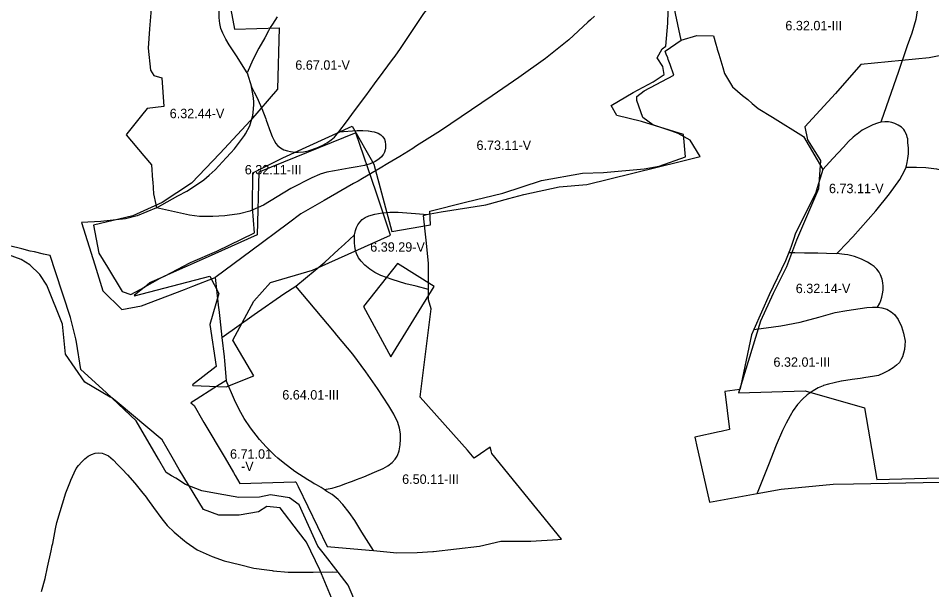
# Model space of a CAD drawing. Extents: x -555156 to -540209, y -1046851 to -1035695.
# Drawn here: x -542138 to -541169, y -1040382 to -1039776 of the extents above; entities that cross this region are included whole.
import ezdxf

# ---------------------------------------------------------------- set-up
doc = ezdxf.new("R2010")
doc.units = 0
for name, color, linetype in [('Vrstva 27', 7, 'Continuous'), ('Vrstva 28', 7, 'Continuous'), ('Vrstva 29', 7, 'Continuous')]:
    doc.layers.add(name, color=color, linetype=linetype)

msp = doc.modelspace()

# ---------------------------------------------------------------- linework, layer by layer
at = {"layer": 'Vrstva 28'}
for points in [[(-541895.16, -1039834.05), (-541906.66, -1039815.74), (-541914.31, -1039804.08), (-541917.9, -1039798.1), (-541921.04, -1039791.98), (-541923.13, -1039786.89), (-541924.32, -1039781.66), (-541924.61, -1039778.6), (-541924.92, -1039775.39), (-541924.97, -1039774.19), (-541925.22, -1039768.66), (-541924.32, -1039761.64), (-541921.93, -1039754.46), (-541917.9, -1039746.69), (-541913.27, -1039739.37), (-541909.09, -1039731.3), (-541907, -1039724.57), (-541905.35, -1039717.4), (-541904.56, -1039692.35), (-541904.34, -1039685.44), (-541904.65, -1039640.7)], [(-541797.96, -1039896.63), (-541789.75, -1039885.71), (-541784.17, -1039878.2), (-541782.31, -1039875.69), (-541769.44, -1039858.36), (-541760.16, -1039845.73), (-541750.87, -1039833.08), (-541741.18, -1039819.9), (-541738.38, -1039816.09), (-541732.54, -1039808.14), (-541707.95, -1039771.07), (-541678.94, -1039734.2), (-541666.43, -1039717.94), (-541658.62, -1039709.58), (-541654.1, -1039705.05), (-541648.89, -1039700.86), (-541641.72, -1039695.83), (-541633.87, -1039690.45), (-541622.3, -1039683.99), (-541614.45, -1039680.24), (-541605.83, -1039676.31), (-541589.27, -1039669.22)], [(-541341.55, -1039665.35), (-541304.33, -1039663.28), (-541293.54, -1039663.28), (-541280.69, -1039664.32), (-541267.4, -1039666.27), (-541256.35, -1039668.96), (-541242.01, -1039673.59), (-541231.7, -1039678.22), (-541223.19, -1039682.82), (-541214.67, -1039688.8), (-541206.31, -1039695.82), (-541199.14, -1039703.89), (-541194.3, -1039713.43), (-541193.61, -1039714.8), (-541190.02, -1039723.48), (-541188.23, -1039727.8), (-541185.69, -1039739.31), (-541183.6, -1039750.97), (-541183.45, -1039759.75), (-541184.2, -1039768.27), (-541185.54, -1039777.23), (-541189.88, -1039791.73)], [(-541434.57, -1039799.28), (-541444.21, -1039754.12), (-541446.3, -1039744.32)], [(-541996.59, -1039755.61), (-541997.65, -1039770.29), (-541998.87, -1039787.19), (-542000.37, -1039807.87), (-541997.75, -1039831.11), (-541994.33, -1039836.86), (-541985.97, -1039839.17), (-541983.75, -1039869.57), (-542001.55, -1039871.8), (-542007.42, -1039879.17), (-542022.88, -1039898.58), (-542023.8, -1039899.74), (-542004.85, -1039922.06), (-541996.97, -1039931.34), (-541995.71, -1039947.75), (-541995.59, -1039949.36), (-541994.6, -1039962.18), (-541992.12, -1039973.6), (-541991.39, -1039976.96)], [(-541526.64, -1039773.69), (-541530.9, -1039777.62), (-541533.63, -1039780.15), (-541554.08, -1039799.06), (-541578.66, -1039818.67), (-541607.15, -1039838.81), (-541635.26, -1039858.48), (-541690.15, -1039895.55), (-541712.7, -1039909.72), (-541716.57, -1039912.15), (-541719.5, -1039913.99), (-541733.15, -1039922.56), (-541745.97, -1039930.1), (-541754.09, -1039934.87), (-541772.75, -1039945.84), (-541777.52, -1039948.65), (-541782.31, -1039951.38), (-541813.66, -1039969.24), (-541838.36, -1039983.43), (-541851.63, -1039993.5), (-541891.57, -1040023.15), (-541928.07, -1040050.24), (-541929.27, -1040051.13)], [(-541863.53, -1039774.68), (-541868.58, -1039782.43), (-541870.85, -1039785.92), (-541872.71, -1039789.39), (-541876.6, -1039796.65), (-541882.87, -1039807.89), (-541889.41, -1039820.18), (-541895.16, -1039834.05)], [(-541434.57, -1039799.28), (-541418.17, -1039794.21), (-541400.56, -1039794.83), (-541397.94, -1039803.52), (-541396.9, -1039806.98), (-541396.39, -1039808.66), (-541394.7, -1039814.27), (-541390.5, -1039828.17), (-541388.56, -1039834.58), (-541380.35, -1039848.73), (-541369.47, -1039857.82), (-541364.09, -1039862.31), (-541359.25, -1039866.35), (-541352.84, -1039871.7), (-541337.74, -1039881), (-541304.71, -1039901.34), (-541284.31, -1039936.3)], [(-541189.88, -1039791.73), (-541194.96, -1039805.18), (-541195.71, -1039807.42), (-541204.1, -1039832.61), (-541222.4, -1039885.18), (-541222.72, -1039886.36)], [(-541704.92, -1039984.14), (-541689.27, -1039981.31), (-541641.85, -1039973.8), (-541617.66, -1039967.28), (-541601.81, -1039963), (-541564.09, -1039954.69), (-541534.97, -1039952.23), (-541435.75, -1039927.99), (-541414.55, -1039922.81), (-541425.06, -1039905.32), (-541437.89, -1039898.11), (-541445.53, -1039895.56), (-541448.75, -1039894.49), (-541464.9, -1039889.12), (-541475.56, -1039881.33), (-541481.81, -1039863.42), (-541481.77, -1039861.63), (-541481.71, -1039859.09), (-541474.12, -1039852.96), (-541442.37, -1039836.44), (-541446.5, -1039825.03), (-541448.41, -1039819.75), (-541448.99, -1039818.16), (-541450.5, -1039813.99), (-541451.59, -1039810.97), (-541434.57, -1039799.28)], [(-541895.16, -1039834.05), (-541890.7, -1039848.68)], [(-541968.79, -1039964.54), (-541959.31, -1039959.26), (-541956.57, -1039957.74), (-541941.41, -1039947.27), (-541935.69, -1039942.4), (-541929.13, -1039936.81), (-541917.63, -1039924), (-541912.69, -1039918.77), (-541908.74, -1039914.58), (-541898.02, -1039900.46), (-541897.02, -1039898.56), (-541892.53, -1039890), (-541889.4, -1039879.01), (-541889.03, -1039875.87), (-541888.09, -1039867.77), (-541888.34, -1039864.75), (-541888.67, -1039860.71), (-541888.87, -1039858.35), (-541889.58, -1039854.59), (-541890.7, -1039848.68)], [(-541890.7, -1039848.68), (-541887.75, -1039854.47), (-541884.72, -1039860.4), (-541883.51, -1039862.76), (-541879.94, -1039870.95), (-541879.63, -1039871.78), (-541875.54, -1039882.56), (-541875.01, -1039883.95), (-541870.4, -1039896.73), (-541868.78, -1039901.34), (-541866.73, -1039905.53), (-541865.03, -1039908.77), (-541863.06, -1039910.99), (-541859.99, -1039913.47), (-541856.49, -1039915.44), (-541852.57, -1039916.8), (-541849.32, -1039917.48), (-541844.88, -1039918)], [(-541222.72, -1039886.36), (-541226.3, -1039887.22), (-541231.42, -1039889.09), (-541237.74, -1039892.08), (-541241.87, -1039894.41), (-541242.44, -1039894.73), (-541247.92, -1039898.92), (-541248.68, -1039899.49), (-541252.27, -1039902.16), (-541257.05, -1039906.86), (-541262.43, -1039912.66), (-541268.23, -1039918.73), (-541273.76, -1039924.77), (-541284.31, -1039936.3)], [(-541195.93, -1039933.84), (-541194.82, -1039928.97), (-541193.97, -1039924.62), (-541193.45, -1039919.92), (-541193.45, -1039913.43), (-541193.97, -1039908.05), (-541194.31, -1039903.95), (-541194.73, -1039902.3), (-541195.25, -1039900.28), (-541196.53, -1039897.12), (-541197.38, -1039895.72), (-541198.4, -1039894.04), (-541200.88, -1039891.65), (-541204.29, -1039889.43), (-541207.79, -1039887.72), (-541211.12, -1039886.7), (-541214.79, -1039885.93), (-541218.72, -1039885.84), (-541222.72, -1039886.36)], [(-541797.96, -1039896.63), (-541778.5, -1039894.92), (-541772.53, -1039895.01), (-541766.95, -1039895.42), (-541766.64, -1039895.44), (-541763.05, -1039896.03), (-541760.57, -1039896.53), (-541759.64, -1039896.72), (-541756.39, -1039898), (-541753.29, -1039899.66), (-541751.25, -1039901.88), (-541749.71, -1039904.35), (-541749.03, -1039906.66), (-541748.82, -1039907.8), (-541748.52, -1039909.39), (-541748.52, -1039912.81), (-541748.64, -1039913.73), (-541748.86, -1039915.54), (-541749.71, -1039918.1), (-541750.74, -1039920.23), (-541750.82, -1039920.41), (-541752.61, -1039922.89), (-541755.75, -1039925.58), (-541759.63, -1039927.97), (-541764.86, -1039930.51), (-541770.69, -1039932.15), (-541778.45, -1039933.65), (-541787.12, -1039934.99), (-541802.69, -1039937.68), (-541810.6, -1039939.18), (-541817.69, -1039941.45), (-541818.52, -1039941.72), (-541826.71, -1039945.23), (-541848.81, -1039956.59), (-541878.09, -1039974.37), (-541892.43, -1039980.5), (-541903.48, -1039983.34), (-541916.41, -1039985.22), (-541918.87, -1039985.58), (-541931.71, -1039986.33), (-541946.05, -1039986.18), (-541956.36, -1039984.83), (-541991.39, -1039976.96)], [(-541844.88, -1039918), (-541841.04, -1039918.08), (-541835.41, -1039917.74), (-541830.31, -1039916.65), (-541829.44, -1039916.46), (-541821.33, -1039913.47), (-541815.1, -1039910.48), (-541809.97, -1039907.66), (-541806.13, -1039905.1), (-541802.63, -1039902.03), (-541797.96, -1039896.63)], [(-541284.31, -1039936.3), (-541290.41, -1039956.05), (-541291.88, -1039960.82), (-541311.16, -1040000), (-541313.2, -1040004.14), (-541315.42, -1040010.54), (-541317.66, -1040016.98), (-541319.39, -1040021.96), (-541320.34, -1040024.31)], [(-541267.48, -1040023.26), (-541252.45, -1040007.83), (-541228.26, -1039980.33), (-541213.62, -1039962.1), (-541202.56, -1039947.01), (-541197.81, -1039937.94), (-541195.93, -1039933.84)], [(-541195.93, -1039933.84), (-541184.84, -1039933.87), (-541174.98, -1039934.47), (-541163.63, -1039935.81), (-541156.91, -1039937.61), (-541150.37, -1039939.26)], [(-541991.39, -1039976.96), (-541968.79, -1039964.54)], [(-541991.39, -1039976.96), (-542012.05, -1039985.71), (-542024.63, -1039988.87), (-542050.65, -1039991.51), (-542071.1, -1039992.55), (-542057, -1040037.69), (-542048.47, -1040065.05), (-542028.38, -1040084.83), (-542007.31, -1040081.07), (-541961.9, -1040063.65), (-541952.83, -1040060.17), (-541929.27, -1040051.13)], [(-541781.34, -1040005.65), (-541780.36, -1040001.24), (-541779.16, -1039997.82), (-541777.8, -1039995.09), (-541775.75, -1039992.35), (-541773.1, -1039989.54), (-541770.12, -1039987.4), (-541766.1, -1039985.44), (-541759.87, -1039983.64), (-541752.11, -1039982.28), (-541744, -1039981.77), (-541735.21, -1039981.85), (-541716.77, -1039983.22), (-541708.24, -1039983.88), (-541704.92, -1039984.14)], [(-541702.87, -1040035.79), (-541705.43, -1040011.5), (-541706.77, -1039998.71), (-541708.18, -1039985.35), (-541704.92, -1039984.14)], [(-542013.22, -1040203.1), (-542045.07, -1040172.93), (-542071.97, -1040148.6), (-542076.53, -1040119.42), (-542077.06, -1040115.99), (-542082.68, -1040093.49), (-542098.63, -1040044.8), (-542104.36, -1040027.66), (-542111.35, -1040026.08), (-542121.12, -1040023.88), (-542125.49, -1040022.89), (-542134.38, -1040020.74), (-542194.7, -1040006.17)], [(-541843.81, -1040060.05), (-541812.97, -1040034.68), (-541798.33, -1040021.34), (-541792.14, -1040015.62), (-541781.34, -1040005.65)], [(-541702.84, -1040063.65), (-541715.94, -1040060.35), (-541726.95, -1040057.54), (-541741.42, -1040053.24), (-541753.45, -1040048.8), (-541759.77, -1040045.73), (-541765.23, -1040042.14), (-541770.44, -1040037.79), (-541774.36, -1040033.6), (-541777.01, -1040030.19), (-541779.23, -1040025.4), (-541780.42, -1040021.82), (-541781.1, -1040018.23), (-541781.36, -1040013.7), (-541781.36, -1040012.67), (-541781.34, -1040005.65)], [(-541320.34, -1040024.31), (-541324, -1040033.35), (-541341.36, -1040069.26), (-541357.7, -1040106.23)], [(-541320.34, -1040024.31), (-541314.2, -1040024.49), (-541303.86, -1040024.78)], [(-541303.86, -1040024.78), (-541300.71, -1040024.87), (-541289.95, -1040024.87), (-541289.63, -1040024.88), (-541280.39, -1040025.21), (-541269.63, -1040025.47)], [(-541269.63, -1040025.47), (-541267.48, -1040023.26)], [(-541226.24, -1040082.41), (-541224.01, -1040078.19), (-541222.9, -1040075.54), (-541221.79, -1040071.95), (-541220.85, -1040068.45), (-541220.25, -1040064.52), (-541220.25, -1040060.17), (-541220.51, -1040056.58), (-541221.45, -1040052.74), (-541223.07, -1040048.3), (-541224.52, -1040045.31), (-541227, -1040042.15), (-541229.9, -1040039.24), (-541232.88, -1040037.02), (-541236.9, -1040034.63), (-541243.15, -1040031.49), (-541250.62, -1040028.8), (-541257.94, -1040026.86), (-541261.26, -1040026.47), (-541269.63, -1040025.47)], [(-541702.84, -1040063.65), (-541702.87, -1040035.79)], [(-541929.27, -1040051.13), (-541925.65, -1040083.3), (-541925.48, -1040084.79), (-541924.39, -1040094.47), (-541922.13, -1040114.5)], [(-541922.13, -1040114.5), (-541887.73, -1040090.13), (-541856.36, -1040068.42), (-541843.81, -1040060.05)], [(-541805.08, -1040274.27), (-541795.97, -1040271.58), (-541791.53, -1040269.98), (-541785.49, -1040267.79), (-541783.68, -1040267.14), (-541779.15, -1040265.32), (-541771.56, -1040262.27), (-541760.03, -1040257.57), (-541750.99, -1040253.48), (-541746.04, -1040250.74), (-541741.43, -1040247.16), (-541738.27, -1040243.82), (-541736.29, -1040240.39), (-541735.94, -1040239.79), (-541734.15, -1040234.86), (-541733.11, -1040228.43), (-541732.51, -1040222.3), (-541732.66, -1040216.77), (-541733.55, -1040210.8), (-541735.5, -1040204.82), (-541739.83, -1040195.85), (-541745.13, -1040187.17), (-541756.89, -1040168.61), (-541769.44, -1040151.08), (-541783.29, -1040132.19), (-541800.07, -1040112.19), (-541802.68, -1040109.08), (-541843.81, -1040060.05)], [(-541661.58, -1040234.29), (-541711.77, -1040177.78), (-541711.38, -1040174.65), (-541702.58, -1040104.07), (-541700.11, -1040084.29), (-541702.82, -1040074.65), (-541702.84, -1040063.65)], [(-541357.7, -1040106.23), (-541329.01, -1040102.33), (-541308.36, -1040098.4), (-541288.75, -1040092.91), (-541271.24, -1040088.2), (-541258.95, -1040085.85), (-541244.84, -1040083.76), (-541237.74, -1040082.71), (-541231.62, -1040082.41), (-541226.24, -1040082.41)], [(-541226.24, -1040082.41), (-541221.76, -1040083.01), (-541216.53, -1040084.65), (-541211.75, -1040087.34), (-541208.32, -1040090.33), (-541204.43, -1040095.41), (-541200.7, -1040102.89), (-541198.61, -1040109.91), (-541197.11, -1040118.43), (-541197.17, -1040122.9), (-541197.68, -1040127.52), (-541198.7, -1040131.36), (-541199.81, -1040134.95), (-541201.18, -1040137.68), (-541203.14, -1040141.01), (-541206.13, -1040143.91), (-541209.8, -1040146.73), (-541214.24, -1040149.72), (-541219.79, -1040152.54), (-541225.42, -1040154.76), (-541231.74, -1040156.12), (-541238.65, -1040157.15), (-541244.88, -1040158.09), (-541253.07, -1040159.28), (-541264.43, -1040160.95), (-541265.06, -1040161.08), (-541272.2, -1040162.6), (-541278.32, -1040163.94), (-541283.57, -1040165.64), (-541283.85, -1040165.73), (-541289.37, -1040167.98), (-541294.75, -1040171.11), (-541300.87, -1040175.3), (-541306.1, -1040179.93), (-541311.18, -1040185.76), (-541315.96, -1040192.04), (-541319.1, -1040197.87), (-541323.43, -1040205.34), (-541327.01, -1040213.26), (-541333.94, -1040228.86), (-541342.16, -1040249.63), (-541353.94, -1040279.88), (-541354.02, -1040280.1)], [(-541357.7, -1040106.23), (-541360.2, -1040111.89), (-541371.51, -1040165.59), (-541372.19, -1040168.82), (-541372.37, -1040169.68), (-541388.48, -1040172), (-541383.58, -1040212.29), (-541392.38, -1040214.26), (-541394.39, -1040214.71), (-541420.18, -1040220.5), (-541417.61, -1040231.74), (-541416.61, -1040236.14), (-541404.52, -1040289.12), (-541354.02, -1040280.1)], [(-541922.13, -1040114.5), (-541919.82, -1040135.02), (-541919.46, -1040139.23), (-541917.66, -1040160.28)], [(-541917.66, -1040160.28), (-541930.65, -1040168.44), (-541949.5, -1040180.28), (-541955.03, -1040183.76), (-541951.73, -1040186.72), (-541942.59, -1040202.29), (-541941.22, -1040204.63), (-541918.85, -1040242.71), (-541910, -1040257.78), (-541908.14, -1040260.95), (-541903.1, -1040269.54), (-541844.72, -1040267.64), (-541843.76, -1040267.61), (-541842.7, -1040269.79), (-541841.93, -1040271.38), (-541841.27, -1040272.75), (-541810.39, -1040336.29), (-541765.83, -1040340.23), (-541761.07, -1040340.65)], [(-541830.86, -1040265.54), (-541844.75, -1040256.73), (-541857.15, -1040247.31), (-541862.79, -1040242.51), (-541866.11, -1040239.69), (-541875.22, -1040230.72), (-541882.09, -1040222.95), (-541891.8, -1040210.55), (-541898.67, -1040200.68), (-541903.75, -1040191.12), (-541908.68, -1040180.66), (-541917.66, -1040160.28)], [(-541354.02, -1040280.1), (-541353.91, -1040280.08), (-541328.75, -1040275.58), (-541273.24, -1040270.09), (-541251.64, -1040269.68), (-541159.46, -1040267.95), (-541142.33, -1040267.63), (-541140.06, -1040267.74), (-541125.53, -1040250.27), (-541098.89, -1040218.25), (-541090.97, -1040208.73), (-541087.56, -1040197.03), (-541086.56, -1040193.6), (-541079.04, -1040167.77), (-541069.44, -1040167.79), (-541021.85, -1040167.91), (-541009.67, -1040167.94)], [(-541798.74, -1040363.44), (-541814.62, -1040342.99), (-541820.24, -1040335.76), (-541840.06, -1040292.05), (-541850.4, -1040284.68), (-541870.66, -1040281.42), (-541882.19, -1040284.08), (-541904.18, -1040284.27), (-541925.94, -1040280.48), (-541943.47, -1040277.42), (-541960.67, -1040270.36), (-541971.18, -1040263.98), (-541975.7, -1040261.24), (-541981.37, -1040257.8), (-541989.51, -1040243.82), (-542013.22, -1040203.1)], [(-541761.07, -1040340.65), (-541743.61, -1040342.19), (-541736.36, -1040342.83), (-541714.83, -1040342.74), (-541698.33, -1040341.53), (-541697.46, -1040341.47), (-541648.64, -1040336.08), (-541626.09, -1040330.6), (-541594.12, -1040330.56), (-541565.68, -1040328.89), (-541561.7, -1040328.66), (-541635.81, -1040237.81), (-541636.5, -1040234.81), (-541637.41, -1040230.88), (-541647.74, -1040237.98), (-541654.3, -1040242.49), (-541661.58, -1040234.29)], [(-542113.48, -1040384.15), (-542109.84, -1040370.36), (-542107.19, -1040358.11), (-542103.48, -1040340.98), (-542102.25, -1040335.31), (-542101.74, -1040332.96), (-542098.62, -1040317.46), (-542097.29, -1040310.86), (-542087.62, -1040279.21), (-542082.92, -1040266.84), (-542082.61, -1040266.01), (-542079.11, -1040257.98), (-542076.64, -1040253.63), (-542074.25, -1040250.21), (-542070.83, -1040246.54), (-542067.59, -1040243.29), (-542064, -1040240.56), (-542060.59, -1040238.77), (-542056.58, -1040237.23), (-542053.08, -1040236.89), (-542049.24, -1040237.4), (-542045.65, -1040238.59), (-542042.58, -1040240.3), (-542037.59, -1040244.21), (-542032.66, -1040249.59), (-542027.88, -1040254.37), (-542022.51, -1040260.33), (-542014.44, -1040269.15), (-542007.42, -1040277.82), (-542002.67, -1040284.02), (-542001, -1040286.19), (-541994.88, -1040294.82), (-541985.92, -1040306.92), (-541980.39, -1040313.95), (-541972.97, -1040321.17), (-541961.99, -1040330.33), (-541960.16, -1040331.6), (-541948.4, -1040339.74), (-541932.45, -1040346.8), (-541919.64, -1040351.51), (-541903.44, -1040355.43), (-541888.28, -1040359.09), (-541874.62, -1040361.02), (-541868.96, -1040361.82), (-541867.89, -1040361.97)], [(-541813.51, -1040275.98), (-541816.78, -1040273.83), (-541821.8, -1040271.02), (-541823.2, -1040270.24), (-541824.14, -1040269.67), (-541826.53, -1040268.2), (-541830.86, -1040265.54)], [(-541813.51, -1040275.98), (-541805.08, -1040274.27)], [(-541761.07, -1040340.65), (-541773.46, -1040321.05), (-541781.08, -1040308.65), (-541787.06, -1040300.13), (-541793.78, -1040291.61), (-541798.71, -1040286.38), (-541805.28, -1040281.3), (-541810.66, -1040277.86), (-541813.51, -1040275.98)], [(-541867.89, -1040361.97), (-541851.94, -1040363.54), (-541837.57, -1040363.54), (-541825.28, -1040363.54), (-541804.63, -1040363.28), (-541798.74, -1040363.44)], [(-541593.76, -1040594.63), (-541593.48, -1040594.1), (-541593.07, -1040584.45), (-541592.73, -1040576.39), (-541600.47, -1040562.6), (-541602.39, -1040559.17), (-541612.08, -1040541.89), (-541641.71, -1040507.59), (-541675.45, -1040495.58), (-541678.57, -1040494.47), (-541685.72, -1040487.24), (-541692.18, -1040480.72), (-541699.7, -1040455.36), (-541701.04, -1040454.15), (-541713.43, -1040442.93), (-541734.8, -1040440.48), (-541740.52, -1040439.82), (-541770.98, -1040406.91), (-541775.35, -1040402.19), (-541779.11, -1040398.91), (-541788.04, -1040377.21), (-541798.74, -1040363.44)]]:
    msp.add_lwpolyline(points, dxfattribs=at)
at = {"layer": 'Vrstva 29'}
for points in [[(-541913.793995, -1039761.056997), (-541908.776002, -1039787.732003), (-541861.243993, -1039786.242), (-541863.086001, -1039851.214993), (-541891.856994, -1039884.342995), (-541924.209005, -1039919.601004), (-541954.566995, -1039951.005008), (-541985.683995, -1039971.582006), (-542016.525999, -1039985.543995), (-542058.395997, -1039995.378992), (-542052.648161, -1040025.004793), (-542043.55, -1040040), (-542028.11, -1040065.86), (-542018.772239, -1040069.005953), (-542004.260376, -1040061.07959), (-541998.596985, -1040056.453979), (-541983.007324, -1040049.544983), (-541955.600005, -1040034.992997), (-541927.551993, -1040022.999001), (-541887.600995, -1040003.474997), (-541889.782004, -1039976.627001), (-541889.248996, -1039939.876005), (-541857.439996, -1039924.238994), (-541783.780006, -1039890.328996), (-541760.929995, -1039930.635002), (-541741.798997, -1040002.199999), (-541700.643819, -1039995.229001), (-541701.35, -1039980.65), (-541663.7, -1039971.24), (-541624.06, -1039961.44), (-541583.06, -1039948.12), (-541539.34, -1039940.24), (-541517, -1039939.79), (-541474.08, -1039935.72), (-541458.17, -1039933.07), (-541429.95, -1039923.14), (-541432.27, -1039899.42), (-541476.76, -1039885.55), (-541502.99, -1039879.18), (-541509.03, -1039868.71), (-541485.77, -1039854.92), (-541464.4, -1039843.4), (-541452.71, -1039835.8), (-541454.05, -1039827.15), (-541460.29, -1039818.14), (-541454.82, -1039808.36), (-541451.052603, -1039805.559199), (-541448.783995, -1039781.229994), (-541448.100046, -1039755.78499)], [(-541132.525002, -1039810.252001), (-541171.348998, -1039818.149008), (-541243.848998, -1039825.098008), (-541271.058007, -1039855.856004), (-541303.409999, -1039891.113), (-541300.681804, -1039905.012783), (-541286.84, -1039926.83), (-541288.95, -1039956.87), (-541312.320767, -1040011.384114), (-541322.870991, -1040039.629992), (-541337.195349, -1040067.820358), (-541350.41, -1040097.44), (-541371.51, -1040165.59), (-541373.975367, -1040173.198263), (-541303.186006, -1040171.083995), (-541240.085007, -1040189.346999), (-541227.106996, -1040265.290998), (-541160.596995, -1040263.506991)], [(-542015.368755, -1040070.152609), (-542015.05, -1040070.26), (-541934.95, -1040049.55), (-541925.52, -1040068.04), (-541935, -1040100.85), (-541928.19, -1040145.26), (-541953.19, -1040164.8), (-541952.907254, -1040165.361052), (-541917.784912, -1040166.820007), (-541888.252991, -1040155.257996), (-541910.393005, -1040117.593018), (-541888.294006, -1040075.999023), (-541870.601013, -1040056.377991), (-541826.01001, -1040043.03302), (-541743.036011, -1040006.143005), (-541758.322021, -1039960.346985), (-541780.046997, -1039897.677002), (-541883.041992, -1039939.338013), (-541884.812012, -1040005.853027), (-541939.958984, -1040030.46698), (-541983.007324, -1040049.544983), (-541987.841999, -1040052.111998), (-542004.260376, -1040061.07959), (-542015.368755, -1040070.152609)], [(-541802.32, -1040399.16), (-541818.1, -1040361.05), (-541832.365216, -1040331.711569), (-541840.870008, -1040320.694006), (-541860.381009, -1040295.358005), (-541874.568951, -1040293.904375), (-541883.46, -1040299.68), (-541903.65, -1040303.14), (-541925.56, -1040303.06), (-541941.69, -1040296.9), (-541967.41, -1040254.67), (-541974.85, -1040241.71), (-541985.48, -1040223.18), (-542033.17, -1040183.19), (-542038.85121, -1040178.446284), (-542040.670993, -1040177.730998), (-542067.469995, -1040162.008008), (-542088.015994, -1040132.458003), (-542091.430697, -1040100.347959), (-542107.778821, -1040058.98796), (-542115.239652, -1040047.746326), (-542126.069125, -1040037.608676), (-542135.028889, -1040031.928801), (-542158.42, -1040023.51)], [(-541743.007996, -1040134.997009), (-541697.023987, -1040060.460022), (-541735.85498, -1040036.143982), (-541771.98999, -1040081.687988), (-541743.007996, -1040134.997009)]]:
    msp.add_lwpolyline(points, dxfattribs=at)

# ---------------------------------------------------------------- texts
at = {"layer": 'Vrstva 27'}
for s, p in [('6.32.01-III', (-541324.116548, -1039788.83)), ('6.67.01-V', (-541844.221006, -1039830.64)), ('6.32.44-V', (-541977.540884, -1039882.02)), ('6.73.11-V', (-541651.931006, -1039915.69)), ('6.32.11-III', (-541897.846548, -1039941.63)), ('6.73.11-V', (-541277.851006, -1039961.55)), ('6.39.29-V', (-541764.720459, -1040023.63)), ('6.32.14-V', (-541313.100884, -1040067.58)), ('6.32.01-III', (-541336.736548, -1040145.65)), ('6.64.01-III', (-541858.076548, -1040180.42)), ('6.71.01', (-541913.523394, -1040243.17)), ('-V', (-541901.827227, -1040256.17)), ('6.50.11-III', (-541730.846548, -1040269.88))]:
    msp.add_text(s, height=10, dxfattribs=at).set_placement(p)

doc.saveas('drawing.dxf')
